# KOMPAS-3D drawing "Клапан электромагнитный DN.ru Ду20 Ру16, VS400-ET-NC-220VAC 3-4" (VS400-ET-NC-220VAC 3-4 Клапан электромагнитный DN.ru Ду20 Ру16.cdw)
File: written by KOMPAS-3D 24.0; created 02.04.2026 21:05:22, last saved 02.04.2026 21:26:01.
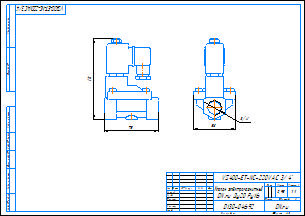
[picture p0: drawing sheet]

Document properties: c3d_UniqueCompID: ef56311e-7521-43dc-8291-0e6108b3d81d; Обозначение: VS400-ET-NC-220VAC 1-2; Наименование: Клапан электромагнитный DN.ru Ду15 Ру16; Автор: artio; Класс точности: c; Знак неуказанной шероховатости: Шероховатость не задана; Рассекать на разрезах: Да; c3d_UniqueCompID: ef56311e-7521-43dc-8291-0e6108b3d81d; Обозначение: VS400-ET-NC-220VAC 3-4; Наименование: Клапан электромагнитный DN.ru Ду20 Ру16; Автор: artio; Класс точности: c; Знак неуказанной шероховатости: Шероховатость не задана; Рассекать на разрезах: Да; c3d_UniqueCompID: ef56311e-7521-43dc-8291-0e6108b3d81d; Обозначение: VS400-ET-NC-220VAC 3-8; Наименование: Клапан электромагнитный DN.ru Ду10 Ру16; Автор: artio; Класс точности: c; Знак неуказанной шероховатости: Шероховатость не задана; Рассекать на разрезах: Да; Автор: artio; Форматы листов документа: A3; Полное имя файла: VS400-ET-NC-220VAC 3-4 Клапан электромагнитный DN.ru Ду20 Ру16.m3d; Масса: 0.954; Наименование: Клапан электромагнитный DN.ru Ду20 Ру16; Количество листов документа: 1; Примечание: D130-04692

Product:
- Body: Тело 1  | qty 1
    Масса: 1.210539
- Part/product: Клапан электромагнитный DN.ru Ду20 Ру16  | designation VS400-ET-NC-220VAC 3-4
    Масса: 0.954
    Раздел спецификации: Прочие изделия
    Примечание: D130-04692
    additional columns: ef56311e-7521-43dc-8291-0e6108b3d81d; VS400-ET-NC-220VAC 3-4; artio; c; Шероховатость не задана; Да

Views: Вид 1, Спереди, Проекционный вид 2
Referenced files in C:\Users\artio\OneDrive\Рабочий стол\Клапан электромагнитный DN.ru VS4x-xT-NC-x\DN10\: VS400-ET-NC-220VAC 3-8 Клапан электромагнитный DN.ru Ду10 Ру16.m3d, VS400-ET-NC-220VAC 3-8 Клапан электромагнитный DN.ru Ду10 Ру16.cdw
Referenced files in C:\Users\artio\OneDrive\Рабочий стол\Клапан электромагнитный DN.ru VS4x-xT-NC-x\DN20\: VS400-ET-NC-220VAC 3-4 Клапан электромагнитный DN.ru Ду20 Ру16.m3d
Referenced files in C:\Users\artio\OneDrive\Рабочий стол\Клапан электромагнитный DN.ru\VS400\VS400-ET-NC\VS400-ET-NC-220VAC\Ду20\: VS400-ET-NC-220VAC 3-4 Клапан электромагнитный DN.ru Ду20 Ру16.m3d
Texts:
  VS400-ET-NC-220VAC 3-4
  Линейный размер
  Клапан электромагнитный
  DN.ru Ду20 Ру16
  VS400-ET-NC-220VAC 3/4"
  VS400-ET-NC-220VAC 3/4"-
  Клапан электромагнитный DN.ru Ду20 Ру16
  VS400-ET-NC-220VAC 3-4 Клапан электромагнитный DN.ru Ду20 Ру16
Dimensions and other numbers on the sheet: 0; 3; 2; 4; 58; 3/4"; 75; 112; 1:1; 1; 0,95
